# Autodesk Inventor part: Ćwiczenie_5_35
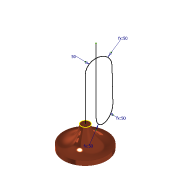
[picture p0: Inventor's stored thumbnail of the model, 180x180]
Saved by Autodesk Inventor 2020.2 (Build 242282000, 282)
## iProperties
Created: 2005-04
Part Number: Ćwiczenie_5_35
Document SubType Name: Modeling
Designer: F.Stasiak
Manufacturer: Standard
Standards Organization: Custom
Density: 1 g/cm^3
Material: Ogólny
Appearance: Miedź — polerowana
Manager: www.cadconsulting.pl
Company: Fabian Stasiak CAD Consulting
Author: F.Stasiak
Subject: Zbiór ćwiczeń. Autodesk Inventor 2020. Kurs podstawowy
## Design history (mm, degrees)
sketch "Szkic2"
  geometry: L1 (0, 0)-(100, 0); L2 (100, 0)-(100, 20); L3 (20, 100)-(0, 100); L4 (0, 100)-(0, 0); A1 r 80 centre (100, 100) between (20, 100) and (100, 20)
  constraints: 8 end point, 2 parallel, 2 point on circle, 1 centre point, 1 horizontal, 1 perpendicular, 1 point on line
  dimensions: "d0" = 200 diameter of L2 L4; "d1" = 100 distance of L3.end L1.start; "d2" = 20 distance of L1.end L2.end; "d3" = 40 diameter of L3.start L4
revolve "Obrót1" sketch "Szkic2" stored, may be unused: angle "d4" = 90 deg
node "Punkt konstrukcyjny1"
  node "Oś konstrukcyjna1"
node "Punkt konstrukcyjny2"
node "Punkt konstrukcyjny3"
node "Punkt konstrukcyjny5"
node "Punkt konstrukcyjny6"
node "Punkt konstrukcyjny8"
sketch "Szkic 3D1" dims "d5" = 50, "d6" = 50 (= d5), "d7" = 50 (= d5), "d8" = 50 (= d5)
sketch "Szkic3"
  geometry: C1 r 20 at (0, 0) reference
node "Bryła1"
node "Korpusy bryłowe"
node "Korpusy powierzchniowe"
